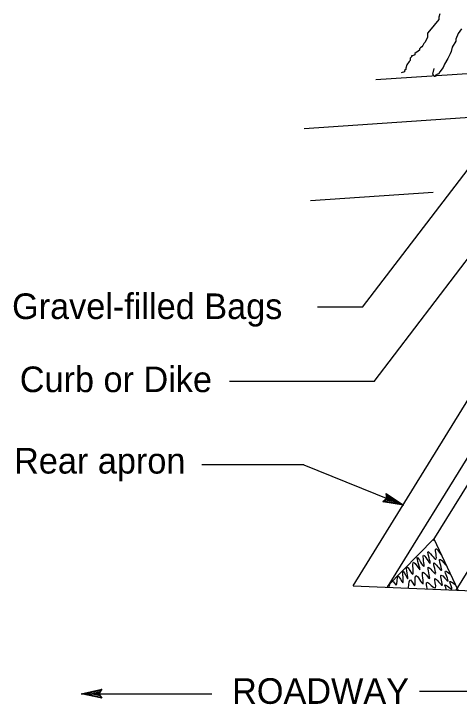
# Model space of a CAD drawing. Extents: x 6707406 to 6714471, y 1868570 to 1872341.
# Drawn here: x 6709544.8 to 6709670, y 1871783.1 to 1871977.2 of the extents above; entities that cross this region are included whole.
import ezdxf

# ---------------------------------------------------------------- set-up
doc = ezdxf.new("R2010")
doc.units = 0
doc.layers.add('57 Undefined', color=7, linetype='Continuous')
doc.layers.add('60 Nongeo Data', color=7, linetype='Continuous')

msp = doc.modelspace()

# ---------------------------------------------------------------- linework, layer by layer
at = {"layer": '57 Undefined'}
for p, q in [((6709642.88, 1871894.69), (6709692.17, 1871959.27)), ((6709646.09, 1871873.81), (6709686.54, 1871926.81)), ((6709642.88, 1871894.69), (6709630.18, 1871894.69)), ((6709646.09, 1871873.81), (6709605.47, 1871873.81)), ((6709626.36, 1871850.36), (6709597.66, 1871850.36)), ((6709626.36, 1871850.36), (6709654.36, 1871839.02)), ((6709563.77, 1871786.05), (6709600.48, 1871786.05)), ((6709695.59, 1871786.69), (6709658.88, 1871786.69))]:
    msp.add_line(p, q, dxfattribs=at)
at = {"layer": '60 Nongeo Data'}
for p, q in [((6709662.75, 1871829.15), (6709733.77, 1871944.23)), ((6709649.88, 1871815.97), (6709720.83, 1871930.94)), ((6709669.18, 1871815.17), (6709741.49, 1871932.34)), ((6709640.23, 1871816.37), (6709709.77, 1871929.07)), ((6709649.5, 1871842.38), (6709649.5, 1871842.38)), ((6709648.54, 1871840), (6709648.54, 1871840)), ((6709654.36, 1871839.02), (6709654.36, 1871839.02)), ((6709569.53, 1871787.33), (6709569.53, 1871787.33)), ((6709563.77, 1871786.05), (6709563.77, 1871786.05)), ((6709569.53, 1871784.77), (6709569.53, 1871784.77))]:
    msp.add_line(p, q, dxfattribs=at)
for points in [[(6709664.6, 1871977.16), (6709664.28, 1871976.2), (6709664.28, 1871975.56), (6709663, 1871973.97), (6709661.72, 1871972.37), (6709661.09, 1871971.73), (6709661.09, 1871971.41), (6709661.09, 1871970.78), (6709661.09, 1871970.46), (6709660.77, 1871969.82), (6709660.45, 1871969.18), (6709660.13, 1871968.86), (6709659.81, 1871968.22), (6709659.49, 1871967.9), (6709659.17, 1871967.59), (6709658.85, 1871967.27), (6709658.85, 1871966.95), (6709658.53, 1871966.63), (6709657.57, 1871965.99), (6709657.57, 1871965.67), (6709656.93, 1871965.35), (6709656.61, 1871965.35), (6709656.61, 1871965.03), (6709656.29, 1871964.71), (6709656.29, 1871964.08), (6709655.97, 1871963.76), (6709655.33, 1871962.8), (6709655.01, 1871961.84), (6709655.01, 1871961.52), (6709654.69, 1871961.2), (6709654.69, 1871960.88), (6709654.69, 1871960.88), (6709653.73, 1871960.56)], [(6709670.66, 1871972.94), (6709669.7, 1871971.66), (6709669.06, 1871970.07), (6709669.06, 1871969.43), (6709668.1, 1871967.83), (6709667.78, 1871966.56), (6709667.46, 1871965.92), (6709666.82, 1871964.64), (6709665.86, 1871963.05), (6709665.54, 1871962.09), (6709664.58, 1871960.81), (6709664.26, 1871960.17), (6709663.94, 1871960.17), (6709663.3, 1871959.86), (6709663.3, 1871959.54), (6709663.3, 1871959.54), (6709662.98, 1871959.54), (6709662.66, 1871960.17), (6709662.98, 1871961.77)], [(6709646.63, 1871958.67), (6709673.79, 1871960.51)], [(6709626.43, 1871944.96), (6709678.6, 1871948.5)], [(6709628.22, 1871924.65), (6709662.68, 1871926.99)], [(6709649.92, 1871816.31), (6709662.86, 1871829.62), (6709669.63, 1871815.28)], [(6709640.23, 1871816.37), (6709687.23, 1871814.41)]]:
    msp.add_lwpolyline(points, dxfattribs=at)
for points in [[(6709649.5, 1871842.38), (6709654.36, 1871839.02), (6709648.54, 1871840), (6709648.86, 1871840.24), (6709653.12, 1871839.52), (6709649.56, 1871841.98), (6709649.62, 1871841.59), (6709651.9, 1871840.02), (6709649.18, 1871840.48), (6709649.49, 1871840.72), (6709650.67, 1871840.52), (6709649.68, 1871841.2), (6709649.73, 1871840.89), (6709648.54, 1871840), (6709649.73, 1871840.89)], [(6709569.53, 1871784.77), (6709563.77, 1871786.05), (6709569.53, 1871787.33), (6709569.32, 1871786.99), (6709565.1, 1871786.06), (6709569.32, 1871785.11), (6709569.12, 1871785.45), (6709566.42, 1871786.05), (6709569.12, 1871786.65), (6709568.91, 1871786.31), (6709567.75, 1871786.05), (6709568.92, 1871785.79), (6709568.76, 1871786.05), (6709569.53, 1871787.33), (6709568.76, 1871786.05)]]:
    msp.add_lwpolyline(points, close=True, dxfattribs=at)
for points in [[(6709650.4, 1871816.23), (6709651.25, 1871817.71), (6709652.35, 1871816.55), (6709652.8, 1871819.2), (6709654.16, 1871817.26), (6709654.29, 1871820.49), (6709655.52, 1871818.36), (6709655.33, 1871821.72), (6709656.95, 1871819.65), (6709657.21, 1871823.02), (6709658.96, 1871820.88), (6709658.24, 1871824.37), (6709660.12, 1871821.85), (6709659.99, 1871825.02), (6709661.87, 1871822.69), (6709661.29, 1871825.99), (6709663.49, 1871823.86), (6709663.43, 1871826.83), (6709664.92, 1871825.09)], [(6709655.78, 1871815.84), (6709656.36, 1871818.04), (6709657.53, 1871816.42), (6709657.85, 1871819.27), (6709659.86, 1871816.94), (6709659.86, 1871820.24), (6709661.68, 1871818.49), (6709661.35, 1871821.59), (6709663.36, 1871819.78), (6709662.91, 1871822.82), (6709665.05, 1871820.75), (6709664.53, 1871823.79), (6709666.28, 1871822.18)], [(6709661.16, 1871815.39), (6709660.96, 1871817.39), (6709663.36, 1871815.84), (6709663.23, 1871818.43), (6709665.24, 1871816.55), (6709664.98, 1871819.4), (6709666.93, 1871817.71), (6709666.15, 1871820.49), (6709667.44, 1871819.72)], [(6709666.41, 1871815.45), (6709666.08, 1871816.68), (6709667.96, 1871815.45), (6709667.44, 1871817.58), (6709669, 1871816.68)]]:
    msp.add_spline(points, degree=3, dxfattribs=at)

# ---------------------------------------------------------------- texts
at = {"layer": '57 Undefined'}
for s, height, p in [('Gravel-filled Bags', 7.1998, (6709544.33, 1871891.37)), ('Curb or Dike', 7.1998, (6709546.5, 1871870.83)), ('Rear apron', 7.2, (6709544.9, 1871847.94)), ('ROADWAY', 7.2, (6709606.19, 1871783.22))]:
    msp.add_text(s, height=height, dxfattribs=at).set_placement(p)

doc.saveas('drawing.dxf')
